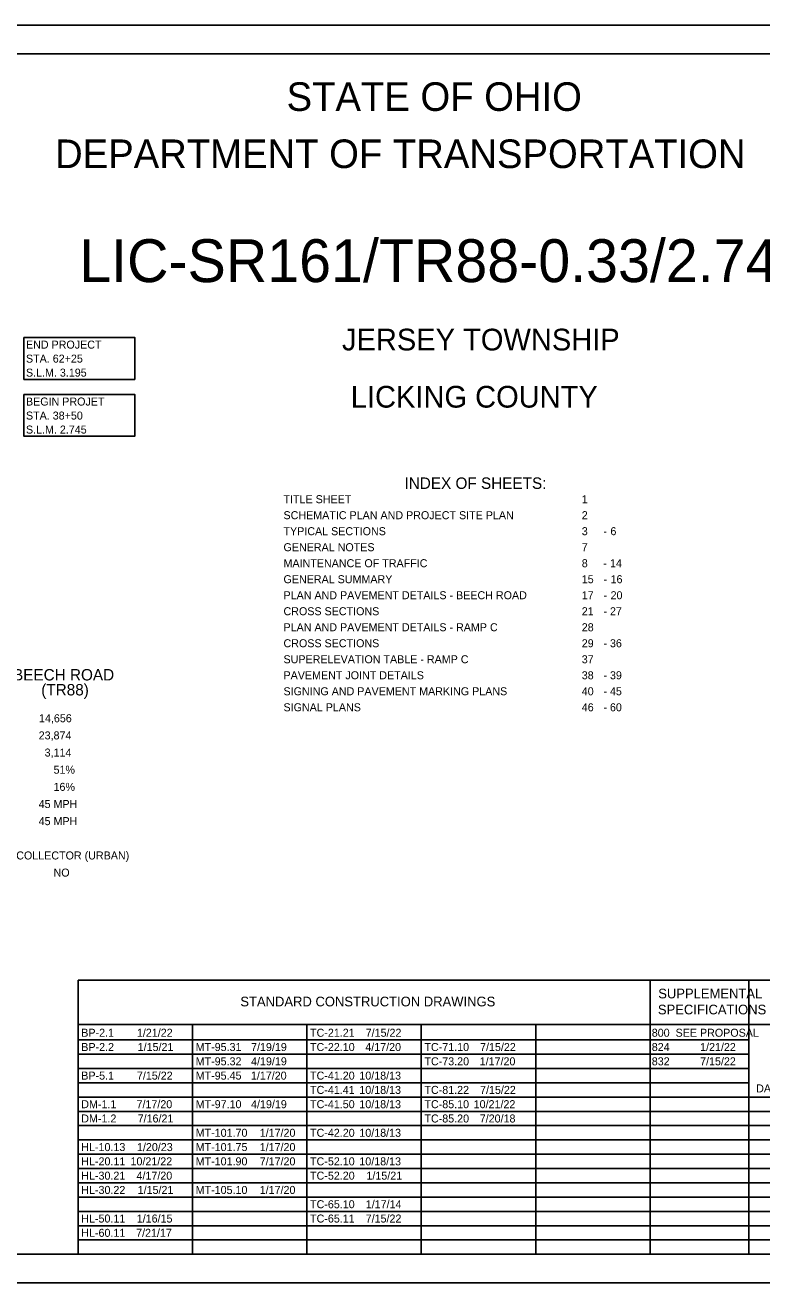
# Model space of a CAD drawing. Extents: x 0 to 91.3, y -0.7 to 22.
# Drawn here: x 9.22 to 22.1, y 0 to 22 of the extents above; entities that cross this region are included whole.
import ezdxf

# ---------------------------------------------------------------- set-up
doc = ezdxf.new("R2010")
doc.units = 0
for name, color, linetype in [('Default', 7, 'Continuous'), ('SH_Border', 7, 'Continuous'), ('SH_Cut_Line', 7, 'Continuous'), ('SH_Data', 7, 'Continuous'), ('SH_Text', 7, 'Continuous')]:
    doc.layers.add(name, color=color, linetype=linetype)

msp = doc.modelspace()

# ---------------------------------------------------------------- linework, layer by layer
at = {"layer": 'SH_Border'}
msp.add_lwpolyline([(1.5, 21.5), (33.5, 21.5), (33.5, 0.5), (1.5, 0.5)], close=True, dxfattribs=at)
at = {"layer": 'SH_Cut_Line'}
msp.add_lwpolyline([(0, 0), (34, 0), (34, 22), (0, 22)], close=True, dxfattribs=at)
at = {"layer": 'SH_Data'}
for p, q in [((10.15, 5.292), (23.6, 5.292)), ((10.15, 0.5), (10.15, 5.292)), ((20.15, 0.5), (20.15, 5.292)), ((21.875, 0.5), (21.875, 5.292)), ((10.15, 4.521), (23.6, 4.521)), ((12.15, 0.5), (12.15, 4.521)), ((14.15, 0.5), (14.15, 4.521)), ((16.15, 0.5), (16.15, 4.521)), ((18.15, 0.5), (18.15, 4.521)), ((10.15, 4.25), (21.875, 4.25)), ((10.15, 4), (21.875, 4)), ((10.15, 3.75), (21.875, 3.75)), ((10.15, 3.5), (21.875, 3.5)), ((10.15, 3.25), (23.6, 3.25)), ((10.15, 3), (23.6, 3)), ((10.15, 2.75), (23.6, 2.75)), ((10.15, 2.5), (23.6, 2.5)), ((10.15, 2.25), (23.6, 2.25)), ((10.15, 2), (23.6, 2)), ((10.15, 1.75), (23.6, 1.75)), ((10.15, 1.5), (23.6, 1.5)), ((10.15, 1.25), (23.6, 1.25)), ((10.15, 1), (23.6, 1)), ((10.15, 0.75), (23.6, 0.75))]:
    msp.add_line(p, q, dxfattribs=at)
at = {"layer": 'SH_Text'}
for points in [[(9.201, 16.537), (11.14, 16.537), (11.14, 15.804), (9.201, 15.804)], [(9.201, 15.54), (11.14, 15.54), (11.14, 14.808), (9.201, 14.808)]]:
    msp.add_lwpolyline(points, close=True, dxfattribs=at)

# ---------------------------------------------------------------- texts
at = {"layer": 'Default'}
for s, p in [('MT-101.70', (12.205, 2.555)), ('1/17/20', (13.325, 2.555)), ('MT-101.75', (12.205, 2.305)), ('1/17/20', (13.325, 2.305)), ('7/17/20', (13.325, 2.055)), ('MT-101.90', (12.205, 2.055)), ('MT-105.10', (12.205, 1.555)), ('1/17/20', (13.325, 1.555))]:
    msp.add_text(s, height=0.14, dxfattribs=at).set_placement(p)
at = {"layer": 'SH_Data'}
for s, height, p in [('1', 0.14, (18.956, 13.638)), ('2', 0.14, (18.956, 13.358)), ('3', 0.14, (18.956, 13.078)), ('6', 0.14, (19.457, 13.078)), ('-', 0.14, (19.334, 13.078)), ('7', 0.14, (18.956, 12.798)), ('8', 0.14, (18.956, 12.518)), ('-', 0.14, (19.333, 12.518)), ('14', 0.14, (19.45, 12.518)), ('15', 0.14, (18.956, 12.238)), ('16', 0.14, (19.46, 12.238)), ('-', 0.14, (19.335, 12.238)), ('17', 0.14, (18.956, 11.958)), ('-', 0.14, (19.335, 11.958)), ('20', 0.14, (19.46, 11.958)), ('21', 0.14, (18.956, 11.678)), ('-', 0.14, (19.337, 11.678)), ('27', 0.14, (19.449, 11.678)), ('28', 0.14, (18.956, 11.398)), ('29', 0.14, (18.956, 11.118)), ('36', 0.14, (19.449, 11.118)), ('-', 0.14, (19.337, 11.118)), ('37', 0.14, (18.956, 10.838)), ('RAMP C     BEECH ROAD', 0.2, (7.6, 10.537)), ('38', 0.14, (18.956, 10.558)), ('-', 0.14, (19.337, 10.558)), ('39', 0.14, (19.449, 10.558)), (' DESIGN DESIGNATION                                     (SR161)          (TR88)', 0.2, (2, 10.275)), ('40', 0.14, (18.956, 10.278)), ('45', 0.14, (19.449, 10.278)), ('46', 0.14, (18.956, 9.998)), ('-', 0.14, (19.337, 10.278)), ('60', 0.14, (19.449, 9.998)), ('-', 0.14, (19.337, 9.998))]:
    msp.add_text(s, height=height, dxfattribs=at).set_placement(p)
at = {"layer": 'SH_Text'}
for s, height, p in [('STATE OF OHIO', 0.5, (13.795, 20.5)), ('DEPARTMENT OF TRANSPORTATION', 0.5, (9.747, 19.5)), ('LIC-SR161/TR88-0.33/2.745', 0.75, (10.169, 17.505)), ('JERSEY TOWNSHIP', 0.38, (14.763, 16.31)), ('END PROJECT', 0.14, (9.238, 16.342)), ('STA. 62+25', 0.14, (9.238, 16.097)), ('S.L.M. 3.195', 0.14, (9.238, 15.852)), ('LICKING COUNTY', 0.38, (14.917, 15.31)), ('BEGIN PROJET ', 0.14, (9.238, 15.346)), ('STA. 38+50', 0.14, (9.238, 15.101)), ('S.L.M. 2.745', 0.14, (9.238, 14.856)), ('                                                      INDEX OF SHEETS:', 0.2, (11.844, 13.888)), ('TITLE SHEET', 0.14, (13.741, 13.638)), ('SCHEMATIC PLAN AND PROJECT SITE PLAN', 0.14, (13.741, 13.358)), ('TYPICAL SECTIONS', 0.14, (13.741, 13.078)), ('GENERAL NOTES', 0.14, (13.741, 12.798)), ('MAINTENANCE OF TRAFFIC', 0.14, (13.741, 12.518)), ('GENERAL SUMMARY', 0.14, (13.741, 12.238)), ('PLAN AND PAVEMENT DETAILS - BEECH ROAD', 0.14, (13.741, 11.958)), ('CROSS SECTIONS', 0.14, (13.741, 11.678)), ('PLAN AND PAVEMENT DETAILS - RAMP C', 0.14, (13.741, 11.398)), ('CROSS SECTIONS', 0.14, (13.741, 11.118)), ('SUPERELEVATION TABLE - RAMP C', 0.14, (13.741, 10.838)), ('PAVEMENT JOINT DETAILS', 0.14, (13.741, 10.558)), ('SIGNING AND PAVEMENT MARKING PLANS', 0.14, (13.741, 10.278)), ('SIGNAL PLANS', 0.14, (13.741, 9.998)), ('14,656', 0.14, (9.466, 9.806)), ('23,874', 0.14, (9.46, 9.506)), ('  3,114', 0.14, (9.46, 9.206)), ('     51%', 0.14, (9.46, 8.906)), ('     16%', 0.14, (9.46, 8.606)), ('45 MPH         ', 0.14, (9.46, 8.306)), ('45 MPH', 0.14, (9.46, 8.006)), ('RAMP C (SR161) - 02 PRINC. ART. FREEWAY (URBAN); BEECH ROAD - 05 MAJ. COLLECTOR (URBAN)                  ', 0.14, (1.994, 7.406)), ('     NO', 0.14, (9.46, 7.106)), ('SUPPLEMENTAL', 0.17, (20.293, 4.976)), ('STANDARD CONSTRUCTION DRAWINGS', 0.17, (12.986, 4.836)), ('SPECIFICATIONS', 0.17, (20.287, 4.696)), ('BP-2.1', 0.14, (10.205, 4.305)), ('1/21/22', 0.14, (11.178, 4.305)), ('TC-21.21', 0.14, (14.205, 4.305)), ('7/15/22', 0.14, (15.178, 4.305)), ('800', 0.14, (20.18, 4.305)), ('SEE PROPOSAL', 0.14, (20.596, 4.305)), ('BP-2.2', 0.14, (10.205, 4.055)), ('1/15/21', 0.14, (11.191, 4.055)), ('MT-95.31', 0.14, (12.205, 4.055)), ('7/19/19', 0.14, (13.174, 4.055)), ('TC-22.10', 0.14, (14.205, 4.055)), ('4/17/20', 0.14, (15.171, 4.055)), ('TC-71.10', 0.14, (16.205, 4.055)), ('7/15/22', 0.14, (17.178, 4.055)), ('824', 0.14, (20.18, 4.055)), ('1/21/22', 0.14, (21.025, 4.055)), ('MT-95.32', 0.14, (12.205, 3.805)), ('4/19/19', 0.14, (13.174, 3.805)), ('TC-73.20', 0.14, (16.205, 3.805)), ('1/17/20', 0.14, (17.171, 3.805)), ('832', 0.14, (20.18, 3.805)), ('7/15/22', 0.14, (21.025, 3.805)), ('BP-5.1', 0.14, (10.205, 3.555)), ('7/15/22', 0.14, (11.178, 3.555)), ('MT-95.45', 0.14, (12.205, 3.555)), ('1/17/20', 0.14, (13.171, 3.555)), ('TC-41.20', 0.14, (14.205, 3.555)), ('10/18/13', 0.14, (15.067, 3.555)), ('TC-41.41', 0.14, (14.205, 3.305)), ('10/18/13', 0.14, (15.067, 3.305)), ('TC-81.22', 0.14, (16.205, 3.305)), ('7/15/22', 0.14, (17.178, 3.305)), ('DATED 2/1/2023', 0.14, (22.005, 3.331)), ('DM-1.1', 0.14, (10.205, 3.055)), ('7/17/20', 0.14, (11.171, 3.055)), ('MT-97.10', 0.14, (12.205, 3.055)), ('4/19/19', 0.14, (13.174, 3.055)), ('TC-41.50', 0.14, (14.205, 3.055)), ('10/18/13', 0.14, (15.067, 3.055)), ('TC-85.10', 0.14, (16.205, 3.055)), ('10/21/22', 0.14, (17.066, 3.055)), ('DM-1.2', 0.14, (10.205, 2.805)), ('7/16/21', 0.14, (11.191, 2.805)), ('TC-85.20', 0.14, (16.205, 2.805)), ('7/20/18', 0.14, (17.172, 2.805)), ('TC-42.20', 0.14, (14.205, 2.555)), ('10/18/13', 0.14, (15.067, 2.555)), ('HL-10.13', 0.14, (10.205, 2.305)), ('1/20/23', 0.14, (11.179, 2.305)), ('10/21/22', 0.14, (11.066, 2.055)), ('10/18/13', 0.14, (15.067, 2.055)), ('HL-20.11', 0.14, (10.205, 2.055)), ('TC-52.10', 0.14, (14.205, 2.055)), ('HL-30.21', 0.14, (10.205, 1.805)), ('4/17/20', 0.14, (11.171, 1.805)), ('TC-52.20', 0.14, (14.205, 1.805)), ('1/15/21', 0.14, (15.191, 1.805)), ('HL-30.22', 0.14, (10.205, 1.555)), ('1/15/21', 0.14, (11.191, 1.555)), ('TC-65.10', 0.14, (14.205, 1.305)), ('1/17/14', 0.14, (15.179, 1.305)), ('HL-50.11', 0.14, (10.205, 1.055)), ('1/16/15', 0.14, (11.175, 1.055)), ('TC-65.11', 0.14, (14.205, 1.055)), ('7/15/22', 0.14, (15.178, 1.055)), ('HL-60.11', 0.14, (10.205, 0.805)), ('7/21/17', 0.14, (11.164, 0.805))]:
    msp.add_text(s, height=height, dxfattribs=at).set_placement(p)

doc.saveas('drawing.dxf')
